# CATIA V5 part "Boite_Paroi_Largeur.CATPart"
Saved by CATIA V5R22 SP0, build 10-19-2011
Part number: Boite_Paroi_Largeur
Bounding box of the stored display mesh (mm): x 0 to 5, y -59.5 to 59.5, z -17.5 to 17.5
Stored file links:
  U:\S9A\PER\CAO\Assemblage\Reservoir_Boite\Boite\Boite_Paroi_Largeur.CATPart
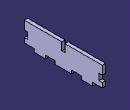
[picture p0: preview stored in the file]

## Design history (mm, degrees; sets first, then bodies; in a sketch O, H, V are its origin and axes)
Body1 (main body)
  Sketch1 on yz-plane, origin (0, 0, 0), H (0, 1, 0), V (0, 0, 1)
    line L1 (-59.5, 17.5) -> (59.5, 17.5)
    line L2 (59.5, 17.5) -> (59.5, -17.5)
    line L3 (59.5, -17.5) -> (-59.5, -17.5)
    line L4 (-59.5, -17.5) -> (-59.5, 17.5)
    length L1 = 119
    length L4 = 35
    horizontal: L1 H, L3 H
    vertical: L2 V, L4 V
    symmetry: L1 L3 H, L4 L2 V
  Pad1: profile Sketch1, direction (1, 0, 0), length 5
  Sketch2 on end face of Pad1, origin (5, 0, 0), H (0, 1, 0), V (0, 0, 1)
    point P1 (-59.5, -12.5)
    line L1 (-59.5, -12.5) -> (-44.5, -12.5)
    line L2 (-44.5, -12.5) -> (-44.5, -17.5)
    line L3 (-44.5, -17.5) -> (-59.5, -17.5)
    line L4 (-59.5, -17.5) -> (-59.5, -12.5)
    point P2 (-44.5, -12.5)
    point P3 (-44.5, -17.5)
    point P4 (-59.5, -17.5)
    reference projected point E1 (-59.5, -17.5) from vertex [face of Pad1 from Sketch1.L3 | end face of Pad1 | face of Pad1 from Sketch1.L4]
    point P5 (59.5, -12.5)
    point P6 (44.5, -12.5)
    point P7 (44.5, -17.5)
    point P8 (59.5, -17.5)
    line L5 (59.5, -12.5) -> (44.5, -12.5)
    line L6 (44.5, -12.5) -> (44.5, -17.5)
    line L7 (44.5, -17.5) -> (59.5, -17.5)
    line L8 (59.5, -17.5) -> (59.5, -12.5)
    length L4 = 5
    length L3 = 15
    horizontal: L1 H, L3 H
    vertical: L2 V, L4 V
    coincidence: P4 E1
    symmetry: P1 P5 V, P2 P6 V, P3 P7 V, P4 P8 V, L1 L5 V, L2 L6 V, L3 L7 V, L4 L8 V
  Pocket1: profile Sketch2, direction (-1, 0, 0), through (limit type 6)
  Sketch3 on end face of Pad1, origin (5, 0, 0), H (0, 1, 0), V (0, 0, 1)
    line L1 (-27.5, -12.5) -> (-12.5, -12.5)
    line L2 (-12.5, -12.5) -> (-12.5, -17.5)
    line L3 (-12.5, -17.5) -> (-27.5, -17.5)
    line L4 (-27.5, -17.5) -> (-27.5, -12.5)
    reference projected line E1 (-59.5, -17.5) -> (59.5, -17.5) from edge [face of Pad1 from Sketch1.L3 | end face of Pad1]
    reference projected line E2 (-44.5, -17.5) -> (-44.5, -12.5) from edge [end face of Pad1 | face of Pocket1 from Sketch2.L2]
    reference projected line E3 (-44.5, -12.5) -> (-59.5, -12.5) from edge [end face of Pad1 | face of Pocket1 from Sketch2.L1]
    distance L4 E2 = 17
    length L3 = 15
    horizontal: L1 H, L3 H
    vertical: L2 V, L4 V
    coincidence: L3 E1, L1 E3
  Pocket2: profile Sketch3, direction (-1, 0, 0), through (limit type 6)
  RectPattern1: of Pocket2, direction 1 instances 2, spacing 40, along edge [face of Pad1 from Sketch1.L3 | end face of Pad1]
  Sketch4 on end face of Pad1, origin (5, 0, 0), H (0, 1, 0), V (0, 0, 1)
    point P1 (-59.5, 4.5)
    line L1 (-59.5, 4.5) -> (-54.5, 4.5)
    line L2 (-54.5, 4.5) -> (-54.5, -5.5)
    line L3 (-54.5, -5.5) -> (-59.5, -5.5)
    line L4 (-59.5, -5.5) -> (-59.5, 4.5)
    point P2 (-54.5, 4.5)
    point P3 (-54.5, -5.5)
    point P4 (-59.5, -5.5)
    reference projected line E1 (-59.5, 17.5) -> (-59.5, -17.5) from edge [face of Pad1 from Sketch1.L4 | end face of Pad1]
    reference projected line E2 (-44.5, -12.5) -> (-59.5, -12.5) from edge [end face of Pad1 | face of Pocket1 from Sketch2.L1]
    point P5 (59.5, 4.5)
    point P6 (54.5, 4.5)
    point P7 (54.5, -5.5)
    point P8 (59.5, -5.5)
    line L5 (59.5, 4.5) -> (54.5, 4.5)
    line L6 (54.5, 4.5) -> (54.5, -5.5)
    line L7 (54.5, -5.5) -> (59.5, -5.5)
    line L8 (59.5, -5.5) -> (59.5, 4.5)
    length L1 = 5
    length L2 = 10
    distance E2 L3 = 7
    horizontal: L1 H, L3 H
    vertical: L2 V, L4 V
    coincidence: E1 L4
    symmetry: P1 P5 V, P2 P6 V, P3 P7 V, P4 P8 V, L1 L5 V, L2 L6 V, L3 L7 V, L4 L8 V
  Pocket3: profile Sketch4, direction (-1, 0, 0), through (limit type 6)
  Sketch5 on end face of Pad1, origin (5, 0, 0), H (0, 1, 0), V (0, 0, 1)
    line L1 (-2.5, 17.5) -> (2.5, 17.5)
    line L2 (2.5, 17.5) -> (2.5, 5.5)
    line L3 (2.5, 5.5) -> (-2.5, 5.5)
    line L4 (-2.5, 5.5) -> (-2.5, 17.5)
    reference projected line E1 (59.5, 17.5) -> (-59.5, 17.5) from edge [face of Pad1 from Sketch1.L1 | end face of Pad1]
    length L1 = 5
    length L4 = 12
    horizontal: L1 H, L3 H
    vertical: L2 V, L4 V
    symmetry: L4 L2 V
    coincidence: L1 E1
  Pocket4: profile Sketch5, direction (-1, 0, 0), through (limit type 6)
